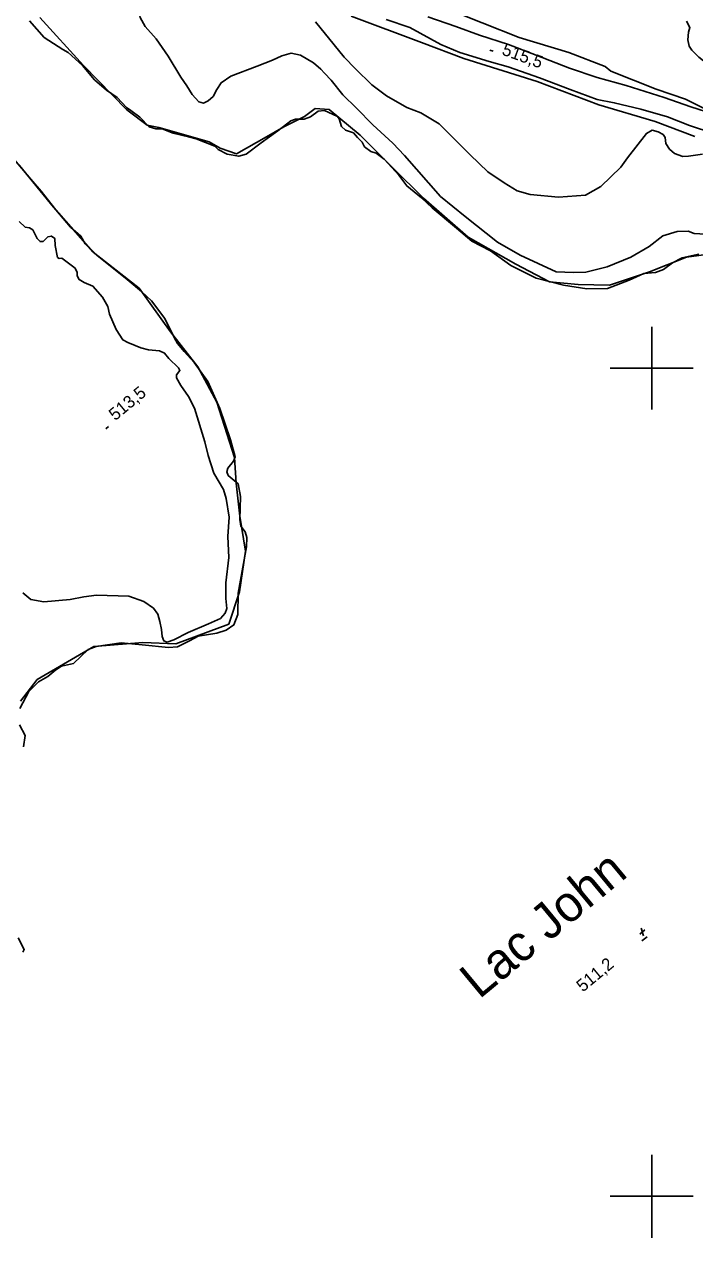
# Model space of a CAD drawing. Extents: x 347059 to 352153, y 6073752 to 6078601.
# Drawn here: x 350472.8 to 350715.6, y 6075585 to 6076024.5 of the extents above; entities that cross this region are included whole.
import ezdxf

# ---------------------------------------------------------------- set-up
doc = ezdxf.new("R2010")
doc.units = 0
for name, color, linetype in [('Level 19', 7, 'Continuous'), ('Level 2', 7, 'Continuous'), ('Level 3', 7, 'Continuous'), ('Level 4', 7, 'Continuous'), ('Level 44', 7, 'Continuous'), ('Level 61', 7, 'Continuous')]:
    doc.layers.add(name, color=color, linetype=linetype)

msp = doc.modelspace()

# ---------------------------------------------------------------- linework, layer by layer
at = {"layer": 'Level 19'}
for points in [[(350603.82, 6076026.24), (350612.39, 6076023.38), (350623.65, 6076017.21), (350630.58, 6076014.34), (350641.2, 6076011), (350648.03, 6076009.09), (350659.39, 6076005.17), (350670.48, 6076000.96), (350680.3, 6075997.27), (350686.42, 6075996.13), (350696.07, 6075993.81), (350705.73, 6075991.03), (350713.67, 6075987.88), (350722.17, 6075985.06), (350729.99, 6075982.04), (350735.32, 6075979.42), (350740.46, 6075975.22), (350742.63, 6075972.61), (350745.2, 6075967.54), (350747.86, 6075959.93), (350751.02, 6075953.78), (350754.98, 6075948.3)], [(350722.55, 6075991.92), (350714.16, 6075994.61), (350704.49, 6075998.04), (350690.76, 6076002.38), (350680.24, 6076005.2), (350670.27, 6076008.61), (350658.12, 6076013.3), (350648.15, 6076017.17), (350637.68, 6076020.55), (350629.04, 6076023.73), (350618.89, 6076027.2)]]:
    msp.add_lwpolyline(points, dxfattribs=at)
at = {"layer": 'Level 2'}
for points in [[(350531.72, 6076002.25), (350529.48, 6076005.34), (350524.96, 6076012.98), (350520.55, 6076019.23), (350516.66, 6076023.76), (350514.8, 6076027.04), (350514.19, 6076029.63), (350513.44, 6076032.09), (350512.02, 6076034.53), (350508.76, 6076037.71), (350503.89, 6076039.92), (350499.18, 6076041.32), (350489.59, 6076044.79), (350483.19, 6076048), (350479.92, 6076050.09), (350477.46, 6076052.32), (350475.62, 6076054.95), (350473.46, 6076061.08), (350470.66, 6076065.46)], [(350718.36, 6075977.5), (350713.37, 6075976.75), (350711.33, 6075976.62), (350708.29, 6075977.67), (350706.46, 6075979.34), (350705.16, 6075981.32), (350704.89, 6075983.52), (350704.1, 6075984.6), (350702.29, 6075985.61), (350700.16, 6075986.22), (350698.11, 6075985.01), (350691.2, 6075976.15), (350688.85, 6075972.79), (350681.64, 6075965.83), (350676.03, 6075962.66), (350666.32, 6075961.92), (350656, 6075962.82), (350651.32, 6075964.22), (350646.59, 6075967.06), (350640.72, 6075971.09), (350634.28, 6075977.19), (350627.81, 6075983.81), (350623.01, 6075988.47), (350616.4, 6075992.42), (350611.39, 6075994.35), (350604, 6075998.57), (350598.64, 6076002.63), (350592.75, 6076008.4), (350588.63, 6076012.58), (350585.05, 6076017.08), (350578.27, 6076025.46)], [(350738.45, 6075988.97), (350739.41, 6075990.19), (350740.83, 6075990.73), (350742.81, 6075990.13), (350746.43, 6075987.31), (350747.84, 6075986.91), (350749.2, 6075987.66), (350749.26, 6075988.38), (350747.56, 6075990.83), (350740.08, 6075996.14), (350732.03, 6076001.63), (350726.02, 6076006.45), (350720.5, 6076009.94), (350717.08, 6076012.67), (350714.59, 6076015.12), (350713.61, 6076016.57), (350713.07, 6076018.93), (350713.35, 6076021.72), (350713.83, 6076023.35), (350712.64, 6076025.68)], [(350719.52, 6075948.46), (350715.34, 6075948.79), (350713.21, 6075949.54), (350709.22, 6075949.5), (350704.09, 6075947.95), (350699.14, 6075944), (350692.45, 6075940.18), (350683.9, 6075936.65), (350676.2, 6075934.8), (350671.68, 6075934.58), (350665.37, 6075934.87), (350652.44, 6075940.85), (350644.21, 6075945.58), (350632.47, 6075954.88), (350623.56, 6075962.13), (350610.56, 6075976.98), (350606.32, 6075981.47), (350599.03, 6075988.09), (350593.07, 6075994.09), (350588.2, 6075998.99), (350583.94, 6076004.27), (350581.59, 6076006.86), (350580.24, 6076008.28), (350577.58, 6076010.6), (350572.83, 6076013.31), (350569.46, 6076014.09), (350566.03, 6076013.06), (350562.71, 6076011.59), (350557.21, 6076009.35), (350547.67, 6076005.69), (350544.14, 6076003.36), (350542.49, 6076000.87), (350541.2, 6075998.43), (350539.4, 6075996.76), (350537.73, 6075996.02), (350536.02, 6075996.45), (350533.66, 6075999.04), (350531.72, 6076002.25)], [(350470.95, 6075953.15), (350473.19, 6075951.01), (350474.71, 6075950.81), (350475.98, 6075950.13)], [(350475.98, 6075950.13), (350477.48, 6075946.95), (350478.57, 6075945.84), (350479.66, 6075945.83), (350481.41, 6075947.58), (350482.67, 6075947.84), (350483.85, 6075946.95), (350484.01, 6075944.39), (350484.85, 6075940.09), (350485.48, 6075939.68), (350486.44, 6075939.82), (350491.2, 6075936.16), (350491.96, 6075934.65), (350491.94, 6075933.41), (350492.71, 6075932.04), (350494.53, 6075931.02), (350497.71, 6075929.67), (350501.13, 6075925.68), (350503.07, 6075922.32), (350503.73, 6075919.5), (350506.15, 6075913.99), (350508.56, 6075910.23), (350510.32, 6075909.29), (350513.01, 6075908.2), (350515.07, 6075907.38), (350517.86, 6075906.65), (350521.85, 6075906.26), (350523.61, 6075905.46), (350525.14, 6075903.52), (350528.67, 6075900.04), (350529.19, 6075899.12), (350527.97, 6075897.54), (350527.96, 6075896.45), (350529.5, 6075893.71), (350532.26, 6075889.7), (350534.49, 6075885.52), (350538.23, 6075873.27), (350539.38, 6075868.3), (350541.45, 6075861.94), (350544.93, 6075855.99), (350545.93, 6075852.77), (350547.01, 6075845.98), (350546.48, 6075839.03), (350546.84, 6075831.35), (350545.77, 6075822.17), (350545.77, 6075816.49), (350546.15, 6075812.88), (350545.52, 6075811.26), (350543.83, 6075809.28), (350539.52, 6075807.35), (350532.19, 6075804.21), (350527.02, 6075801.55), (350524.61, 6075800.71), (350523.34, 6075801.25), (350522.73, 6075802.76), (350522.48, 6075805.26), (350521.9, 6075808.15)], [(350521.9, 6075808.15), (350521.16, 6075810.91), (350519.57, 6075813.07), (350516.17, 6075815.45), (350510.69, 6075817.42), (350499.02, 6075817.75), (350494.43, 6075817.09), (350489.39, 6075816.17), (350479.96, 6075815.3), (350475.26, 6075816.21), (350472.34, 6075818.57)]]:
    msp.add_lwpolyline(points, dxfattribs=at)
at = {"layer": 'Level 3'}
for p, q in [((350641.44, 6076015.17), (350642.56, 6076014.76)), ((350502.39, 6075878.03), (350503.31, 6075878.8)), ((350695.77, 6075695.01), (350697.57, 6075696.5)), ((350696.22, 6075697.14), (350697.05, 6075694.4)), ((350696.48, 6075692.49), (350698.33, 6075694.02))]:
    msp.add_line(p, q, dxfattribs=at)
at = {"layer": 'Level 4'}
for points in [[(350474.78, 6076025.73), (350480, 6076019.79), (350486.78, 6076015.37), (350488.75, 6076014.35), (350493.88, 6076009.55), (350498.26, 6076004.36), (350502.62, 6076000.68), (350506.46, 6075998.01), (350509.84, 6075994.42), (350511.46, 6075993.26), (350514.62, 6075990.87), (350518.05, 6075987.41), (350520.51, 6075986.72), (350522.77, 6075986.63), (350526.72, 6075985.12), (350532.25, 6075983.8), (350535.07, 6075983.03), (350541.88, 6075980.42), (350543, 6075979.23), (350546.31, 6075977.49), (350550.49, 6075976.72), (350553.16, 6075977.43), (350558.63, 6075981.55), (350564.67, 6075985.91), (350569.32, 6075989.57), (350571.06, 6075990.12), (350574.21, 6075990.15), (350576.43, 6075990.95), (350579.2, 6075993.11), (350581.5, 6075993.35), (350586.19, 6075991.11), (350586.81, 6075990.25), (350587.7, 6075987.49), (350589.1, 6075986.15), (350592.02, 6075985.16), (350593.51, 6075983.51), (350595.2, 6075981.8), (350595.99, 6075980.18), (350598.35, 6075978.49), (350600.27, 6075977.89), (350603.1, 6075975.62), (350608.41, 6075969.93), (350611.32, 6075965.98), (350616.68, 6075961.71), (350620.53, 6075958), (350629.35, 6075950.69), (350634.86, 6075945.95)], [(350551.96, 6075827.85), (350553.34, 6075835.29), (350553.46, 6075838.65), (350552.83, 6075840.71), (350551.26, 6075842.73), (350550.87, 6075845.14), (350551.1, 6075853.52), (350550.23, 6075858.1), (350546.69, 6075861.14), (350546.2, 6075862.48), (350546.49, 6075863.79), (350548.62, 6075866.25), (350549.15, 6075867.91), (350547.52, 6075874.06), (350543.67, 6075885.42), (350539.33, 6075895.17), (350534.38, 6075901.98), (350530.68, 6075906.04), (350528.32, 6075908.93), (350527.26, 6075910.78), (350523.71, 6075918.01), (350518.95, 6075924.38), (350515.23, 6075927.74), (350510.03, 6075932.07), (350499.15, 6075940.87), (350494.92, 6075945.03), (350493.32, 6075947.81), (350489.58, 6075951.01), (350484.24, 6075957.36), (350478.93, 6075964.14), (350475.21, 6075968.42), (350467.33, 6075977.7)], [(350634.86, 6075945.95), (350641.61, 6075942.47), (350648.97, 6075937.14), (350658.12, 6075932.56), (350668.06, 6075930.07), (350676.53, 6075928.65), (350683.97, 6075928.86), (350691.88, 6075931.83), (350697.19, 6075934.29), (350701.35, 6075934.65), (350704.34, 6075935.7), (350707.54, 6075938.07), (350710.99, 6075939.97), (350717.08, 6075941.27)], [(350471.28, 6075776.64), (350474.51, 6075782.9), (350477.97, 6075786.4), (350481.41, 6075788.28), (350484.2, 6075790.76), (350486.33, 6075792.01), (350490.63, 6075793.02), (350496.01, 6075798.05), (350498.83, 6075799.11), (350507.9, 6075800.47), (350515.53, 6075799.71), (350525.03, 6075798.78), (350528.26, 6075798.98), (350532.63, 6075801.19), (350535.84, 6075802.88), (350542.57, 6075803.95), (350545.89, 6075805.06), (350548.67, 6075807), (350550.1, 6075810.77), (350550.27, 6075818.49), (350551.96, 6075827.85)], [(350472.55, 6075762.78), (350473.11, 6075766.88), (350471.05, 6075770.76)], [(350472.29, 6075688.45), (350472.84, 6075689.43), (350470.56, 6075693.57)]]:
    msp.add_lwpolyline(points, dxfattribs=at)
at = {"layer": 'Level 44'}
for points in [[(350591.13, 6076027.5), (350616.65, 6076017.97), (350631.95, 6076012.09), (350658.51, 6076003.85), (350680.83, 6075995.4), (350701.3, 6075989.34), (350715.61, 6075983.85)], [(350725.92, 6075990.53), (350712.24, 6075997.44), (350701.61, 6076001.04), (350685.25, 6076007.55), (350683.2, 6076009.29), (350669.97, 6076014.29), (350652.05, 6076019.78), (350625.26, 6076030.42)], [(350726.02, 6075941.95), (350712.6, 6075940.23), (350699.17, 6075934.9), (350684.77, 6075930.01), (350673.43, 6075930.25), (350662.99, 6075931.24), (350650.85, 6075937.64), (350633.53, 6075947.46), (350617.35, 6075961.59), (350606.3, 6075972.58), (350594.42, 6075984.4), (350583.28, 6075993.65), (350578.19, 6075993.97), (350574.29, 6075991.16), (350566.75, 6075987.44), (350560.53, 6075983.77), (350549.71, 6075977.61), (350543.8, 6075979.67), (350539.81, 6075981.97), (350521.56, 6075987.13), (350517.36, 6075988.03), (350509.96, 6075993.59), (350494.31, 6076009.63), (350478.52, 6076026.96)], [(350471.09, 6075973.36), (350483.37, 6075958.32), (350497.74, 6075942.02), (350514.48, 6075928.92), (350525.83, 6075913.16), (350535.65, 6075900.4), (350542.59, 6075887.66), (350548.98, 6075867.65), (350549.56, 6075858.28), (350550.87, 6075846.34), (350552.94, 6075833.68), (350550.78, 6075819.01), (350546.85, 6075807.25), (350527.75, 6075800.08), (350515.72, 6075800.63), (350498.06, 6075799.21), (350489.88, 6075794.5), (350477.5, 6075787.19), (350471.41, 6075779.38)]]:
    msp.add_lwpolyline(points, dxfattribs=at)
at = {"layer": 'Level 61'}
for p, q in [((350700, 6075885), (350700, 6075915)), ((350685, 6075900), (350715, 6075900)), ((350700, 6075585), (350700, 6075615)), ((350685, 6075600), (350715, 6075600))]:
    msp.add_line(p, q, dxfattribs=at)

# ---------------------------------------------------------------- texts
at = {"layer": 'Level 3'}
for s, rotation, p in [('515,5', 339.8897, (350645.47, 6076013.64)), ('513,5', 39.62, (350505.75, 6075880.74)), ('  511,2', 39.57, (350672.5, 6075671.66))]:
    msp.add_text(s, height=4.5, rotation=rotation, dxfattribs=at).set_placement(p)
at = {"layer": 'Level 4'}
msp.add_text('Lac John', height=13, rotation=39.6435, dxfattribs=at).set_placement((350637.53, 6075671.18))

doc.saveas('drawing.dxf')
